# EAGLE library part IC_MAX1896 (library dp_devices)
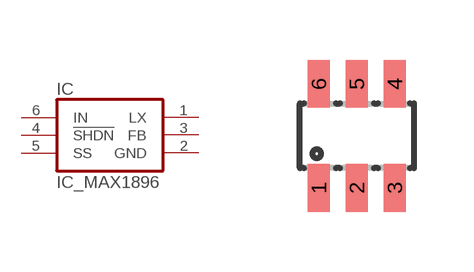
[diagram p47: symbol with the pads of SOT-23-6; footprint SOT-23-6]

Designator prefix IC

## IC_MAX1896  [SOT-23-6]
1  LX
2  GND
3  FB
4  !SHDN
5  SS
6  IN

## Footprint SOT-23-6 (pad centres in mm)
smd 0.55 x 1.2: 1 -0.95,-1.3; 2 0,-1.3; 3 0.95,-1.3; 4 0.95,1.3; 5 0,1.3; 6 -0.95,1.3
